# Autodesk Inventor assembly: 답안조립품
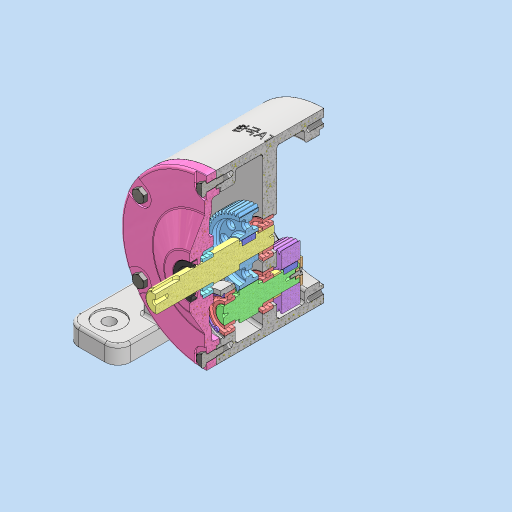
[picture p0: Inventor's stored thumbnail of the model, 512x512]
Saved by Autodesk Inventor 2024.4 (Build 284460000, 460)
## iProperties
Created: 2025-12
Part Number: 답안조립품
Document SubType Name: Assembly
Designer: home
Author: home
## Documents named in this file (17)
- C:\Users\home\Desktop\751203V1017\답안조립품.iam
- C:\Users\home\Desktop\751203V1017\본체.ipt
- C:\Users\home\Desktop\751203V1017\깊은 홈 볼 베어링 6004\깊은 홈 볼 베어링 6004\깊은 홈 볼 베어링 6004.ipt
- C:\Users\home\Desktop\751203V1017\기어 축\기어 축\기어 축.ipt
- C:\Users\home\Desktop\751203V1017\C형 멈춤링 구멍용 42\C형 멈춤링 구멍용 42\C형 멈춤링 구멍용 42.ipt
- C:\Users\home\Desktop\751203V1017\칼라 1\칼라 1\칼라 1.ipt
- C:\Users\home\Desktop\751203V1017\평행 키 6x6x16\평행 키 6x6x16\평행 키 6x6x16.ipt
- C:\Users\home\Desktop\751203V1017\구동 기어\구동 기어\구동 기어.ipt
- C:\Users\home\Desktop\751203V1017\엔드 캡\엔드 캡\엔드 캡.ipt
- C:\Users\home\Desktop\751203V1017\6각 구멍붙이 볼트 M4x10\6각 구멍붙이 볼트 M4x10\6각 구멍붙이 볼트 M4x10.ipt
- C:\Users\home\Desktop\751203V1017\출력 축\출력 축\출력 축.ipt
- C:\Users\home\Desktop\751203V1017\칼라 2\칼라 2\칼라 2.ipt
- C:\Users\home\Desktop\751203V1017\종동 기어\종동 기어\종동 기어.ipt
- C:\Users\home\Desktop\751203V1017\깊은 홈 볼 베어링 6005\깊은 홈 볼 베어링 6005\깊은 홈 볼 베어링 6005.ipt
- C:\Users\home\Desktop\751203V1017\커버\커버\커버.ipt
- C:\Users\home\Desktop\751203V1017\오일 실 25 40 8\오일 실 25 40 8\오일 실 25 40 8.ipt
- C:\Users\home\Desktop\751203V1017\6각 머리 볼트 M8x20\6각 머리 볼트 M8x20\6각 머리 볼트 M8x20.ipt
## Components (9 placed, 4 different names)
1. C형 멈춤링 구멍용 42:1 — 각도:5
2. 구동 기어:1
3. 6각 구멍붙이 볼트 M4x10:1
4. 6각 머리 볼트 M8x20:1
5. 6각 머리 볼트 M8x20:2
6. 6각 머리 볼트 M8x20:3
7. 6각 머리 볼트 M8x20:4
8. 6각 머리 볼트 M8x20:5
9. 6각 머리 볼트 M8x20:6
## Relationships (1: Angle 1)
- 각도:5 [Angle]: C형 멈춤링 구멍용 42:1
